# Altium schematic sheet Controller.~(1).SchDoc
size OrCAD B
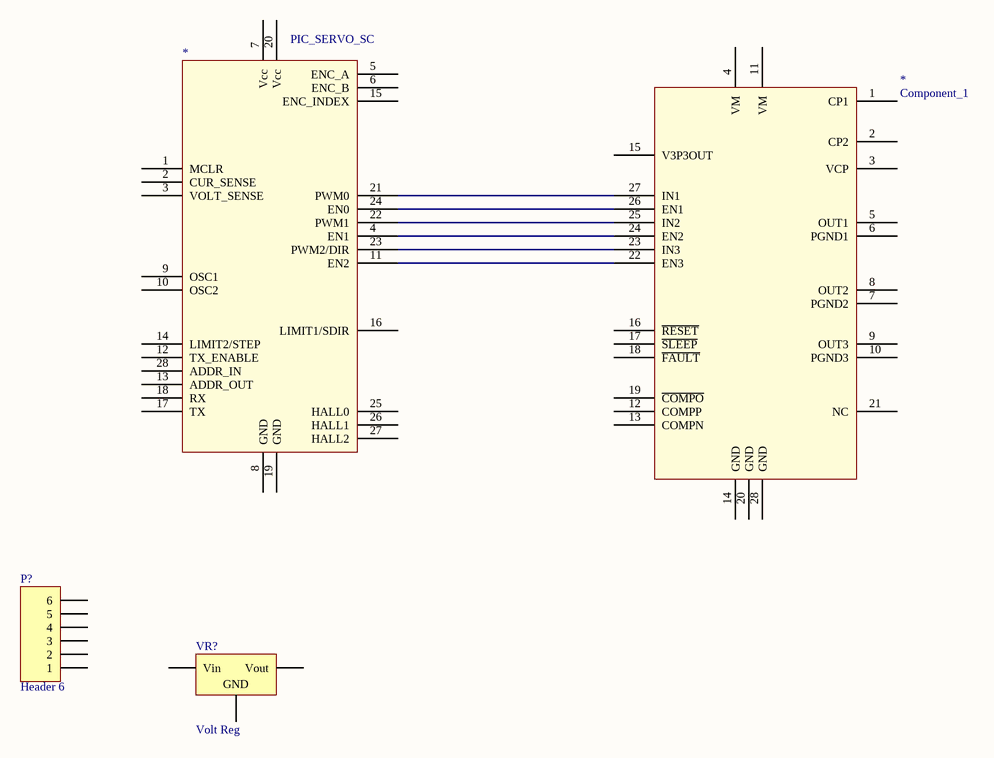
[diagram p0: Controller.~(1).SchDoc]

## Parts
(Parts that share a designator on the sheet are numbered #1, #2 ... from top to bottom, then left to right.)
*#1  PIC_SERVO_SC
*#2  Component_1
P?  Header 6  [HDR1X6]
VR?  Volt Reg  [D2PAK_N]

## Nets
Net*#1_4: *#1.4(EN1) *#2.24(EN2)
Net*#1_11: *#1.11(EN2) *#2.22(EN3)
Net*#1_21: *#1.21(PWM0) *#2.27(IN1)
Net*#1_22: *#1.22(PWM1) *#2.25(IN2)
Net*#1_23: *#1.23(PWM2/DIR) *#2.23(IN3)
Net*#1_24: *#1.24(EN0) *#2.26(EN1)

Not connected (* = marked no-connect by the designer): *#1 1(MCLR) 2(CUR_SENSE) 3(VOLT_SENSE) 5(ENC_A) 6(ENC_B) 7(Vcc) 8(GND) 9(OSC1) 10(OSC2) 12(TX_ENABLE) 13(ADDR_OUT) 14(LIMIT2/STEP) 15(ENC_INDEX) 16(LIMIT1/SDIR) 17(TX) 18(RX) 19(GND) 20(Vcc) 25(HALL0) 26(HALL1) 27(HALL2) 28(ADDR_IN); *#2 1(CP1) 2(CP2) 3(VCP) 4(VM) 5(OUT1) 6(PGND1) 7(PGND2) 8(OUT2) 9(OUT3) 10(PGND3) 11(VM) 12(COMPP) 13(COMPN) 14(GND) 15(V3P3OUT) 16(~{RESET}) 17(~{SLEEP}) 18(~{FAULT}) 19(~{COMPO}) 20(GND) 21(NC) 28(GND); P? 1 2 3 4 5 6; VR? 1(Vin) 2(GND) 3(Vout)

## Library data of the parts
P? = Header 6: Header, 6-Pin
VR? = Volt Reg: Voltage Regulator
